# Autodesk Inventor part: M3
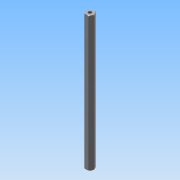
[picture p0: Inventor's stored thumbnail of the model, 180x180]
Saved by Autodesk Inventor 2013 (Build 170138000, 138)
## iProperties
Created: 2012-08
Part Number: M3
Material: Stahl
Document SubType Name: Modeling
Designer: rYan
Density: 7.85 g/cm^3
Mass: 16.8319 g
Surface Area: 27.1713 cm^2
Volume: 2.1442 cm^3
Author: rYan
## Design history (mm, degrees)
derived "Abstandsbolzen Typ A.ipt"
feature "Volumenkörper1::Abstandsbolzen Typ A.ipt"
tag "Bezeichnung1"
node "Volumenkörper1"
other parameters: "SW" = 5.5, "d2" = 0, "d16" = 45 deg
